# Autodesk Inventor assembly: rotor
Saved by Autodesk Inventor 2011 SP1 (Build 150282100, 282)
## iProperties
Created: 2010-12
Part Number: rotor
Document SubType Name: Assembly
Designer: eric
Author: eric
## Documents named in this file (5)
- D:\eduinventor\maquettesaip2011\machineàpain\Workspace\rotor.iam
- D:\eduinventor\maquettesaip2011\machineàpain\Workspace\axe moteur.ipt
- D:\eduinventor\maquettesaip2011\machineàpain\Workspace\poulie motrice.ipt
- D:\eduinventor\maquettesaip2011\machineàpain\Workspace\flasque de poulie motrice.ipt
- D:\eduinventor\maquettesaip2011\machineàpain\Workspace\Anneau élastique pour arbre, 8x0.8.ipt
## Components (4 placed, 4 different names)
1. axe moteur:1
2. poulie motrice:1
3. flasque de poulie motrice:1
4. Anneau élastique pour arbre, 8x0.8:1
